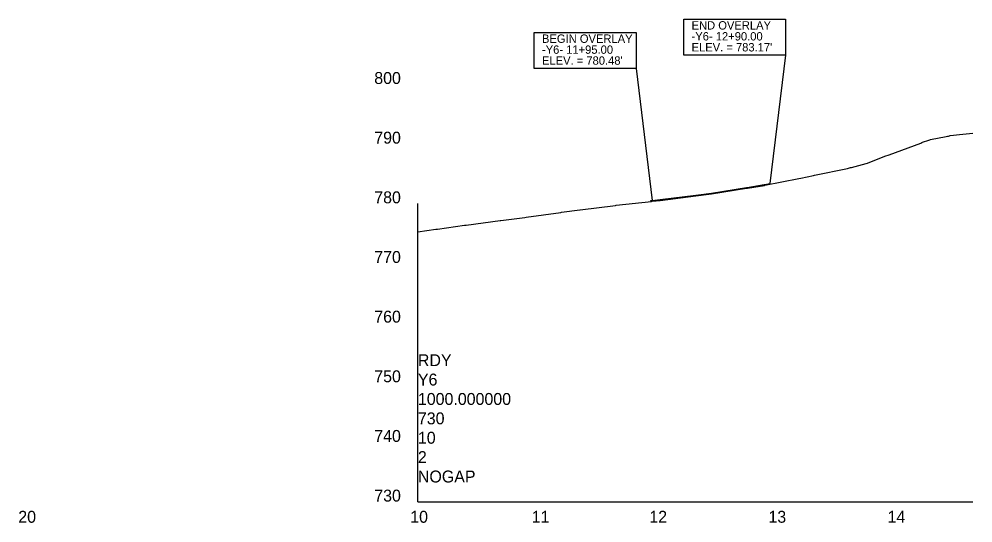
# Model space of a CAD drawing. Extents: x 579185 to 595036, y -53221 to -44640.
# Drawn here: x 585926 to 586726, y -49553 to -49130 of the extents above; entities that cross this region are included whole.
import ezdxf

# ---------------------------------------------------------------- set-up
doc = ezdxf.new("R2010")
doc.units = 0
for name, color, linetype in [('Exist Profile Cell', 7, 'Continuous'), ('Exist Vertical Profile Ground Line', 7, 'Continuous'), ('Exist Vertical Profile Horizontal Axis Label Major', 7, 'Continuous'), ('Exist Vertical Profile Vertical Axis Label', 7, 'Continuous'), ('Prop Grid Mask', 7, 'Continuous'), ('Prop Vertical Profile Curve Label', 7, 'Continuous'), ('Prop Vertical Profile Grade', 7, 'Continuous'), ('Prop VPI Label', 7, 'Continuous')]:
    doc.layers.add(name, color=color, linetype=linetype)

msp = doc.modelspace()

# ---------------------------------------------------------------- linework, layer by layer
at = {"layer": 'Exist Profile Cell'}
for q in [(586260.77, -49285.12), (586725.99, -49535.12), (586260.77, -49535.12)]:
    msp.add_line((586260.77, -49535.12), q, dxfattribs=at)
at = {"layer": 'Exist Vertical Profile Ground Line'}
msp.add_lwpolyline([(586260.77, -49308.69), (586275.8, -49306.63), (586277.07, -49306.44), (586299.77, -49303.33), (586301.13, -49303.16), (586329.86, -49299.38), (586330.28, -49299.33), (586350.27, -49296.69), (586351.4, -49296.56), (586380.65, -49292.52), (586381.27, -49292.44), (586396.4, -49290.35), (586396.9, -49290.28), (586426.4, -49286.6), (586427.07, -49286.51), (586456.48, -49283.25), (586457.07, -49283.18), (586463.87, -49282.43), (586493.84, -49278.6), (586506.85, -49276.93), (586536.29, -49272.22), (586536.96, -49272.12), (586551.25, -49269.83), (586551.63, -49269.77), (586580, -49264.05), (586581.65, -49263.71), (586592.49, -49261.53), (586593.34, -49261.35), (586620.89, -49255.57), (586623.39, -49255), (586624.13, -49254.84), (586636.5, -49251.4), (586637.55, -49251.16), (586652.23, -49245.45), (586655.7, -49244.25), (586682.27, -49234.35), (586683.06, -49234.05), (586683.85, -49233.76), (586689.01, -49231.84), (586689.85, -49231.57), (586690.57, -49231.37), (586703.64, -49228.99), (586704.58, -49228.71), (586705.38, -49228.49), (586706.29, -49228.33), (586707.05, -49228.18), (586709.7, -49227.8), (586712.14, -49227.47), (586714.75, -49227.21), (586725.99, -49226.16)], dxfattribs=at)
at = {"layer": 'Prop Grid Mask'}
for points in [[(586483.61, -49130.47), (586569.01, -49130.47), (586569.01, -49160.66), (586483.61, -49160.66)], [(586358.21, -49141.63), (586443.61, -49141.63), (586443.61, -49171.81), (586358.21, -49171.81)]]:
    msp.add_lwpolyline(points, close=True, dxfattribs=at)
at = {"layer": 'Prop Vertical Profile Curve Label'}
for p, q in [((586569.01, -49160.66), (586555.77, -49268.3)), ((586443.61, -49171.81), (586457, -49282.56))]:
    msp.add_line(p, q, dxfattribs=at)
at = {"layer": 'Prop Vertical Profile Grade'}
msp.add_lwpolyline([(586455.77, -49282.7), (586456.41, -49282.63), (586457, -49282.56), (586463.8, -49281.81), (586493.76, -49277.98), (586506.76, -49276.31), (586536.19, -49271.61), (586536.86, -49271.5), (586551.15, -49269.21), (586551.51, -49269.15), (586555.77, -49268.3)], dxfattribs=at)

# ---------------------------------------------------------------- texts
at = {"layer": 'Exist Profile Cell'}
for s, p in [('RDY', (586260.77, -49421.37)), ('Y6', (586260.77, -49437.62)), ('1000.000000', (586260.77, -49453.87)), ('730', (586260.77, -49470.12)), ('10', (586260.77, -49486.37)), ('2', (586260.77, -49502.62)), ('NOGAP', (586260.77, -49518.87))]:
    msp.add_text(s, height=10, dxfattribs=at).set_placement(p)
at = {"layer": 'Exist Vertical Profile Horizontal Axis Label Major'}
for s, p in [('20', (585925.81, -49552.62)), ('10', (586254.35, -49552.62)), ('11', (586356.19, -49552.62)), ('12', (586454.74, -49552.62)), ('13', (586554.58, -49552.62)), ('14', (586654.42, -49552.62))]:
    msp.add_text(s, height=10, dxfattribs=at).set_placement(p)
at = {"layer": 'Exist Vertical Profile Vertical Axis Label'}
for s, p in [('800', (586224.2, -49184.87)), ('790', (586224.2, -49234.87)), ('780', (586224.2, -49284.87)), ('770', (586224.2, -49334.87)), ('760', (586224.2, -49384.87)), ('750', (586224.2, -49434.87)), ('740', (586224.2, -49484.87)), ('730', (586224.2, -49534.87))]:
    msp.add_text(s, height=10, dxfattribs=at).set_placement(p)
at = {"layer": 'Prop VPI Label'}
for s, p in [('END OVERLAY', (586490.16, -49139.23)), ('BEGIN OVERLAY', (586364.77, -49150.39)), ('-Y6- 12+90.00', (586490.16, -49148.41)), ('-Y6- 11+95.00', (586364.77, -49159.56)), ("ELEV. = 783.17'", (586490.16, -49157.59)), ("ELEV. = 780.48'", (586364.77, -49168.74))]:
    msp.add_text(s, height=7, dxfattribs=at).set_placement(p)

doc.saveas('drawing.dxf')
